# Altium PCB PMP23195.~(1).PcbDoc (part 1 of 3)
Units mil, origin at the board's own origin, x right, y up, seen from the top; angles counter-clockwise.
Board outline 3600 x 3000 mil, 4 copper layers (Top Layer, Signal Layer 1, Signal Layer 2, Bottom Layer), stack 39.6 mil thick; 143 components, 62 nets, 279 pads, 97 vias.
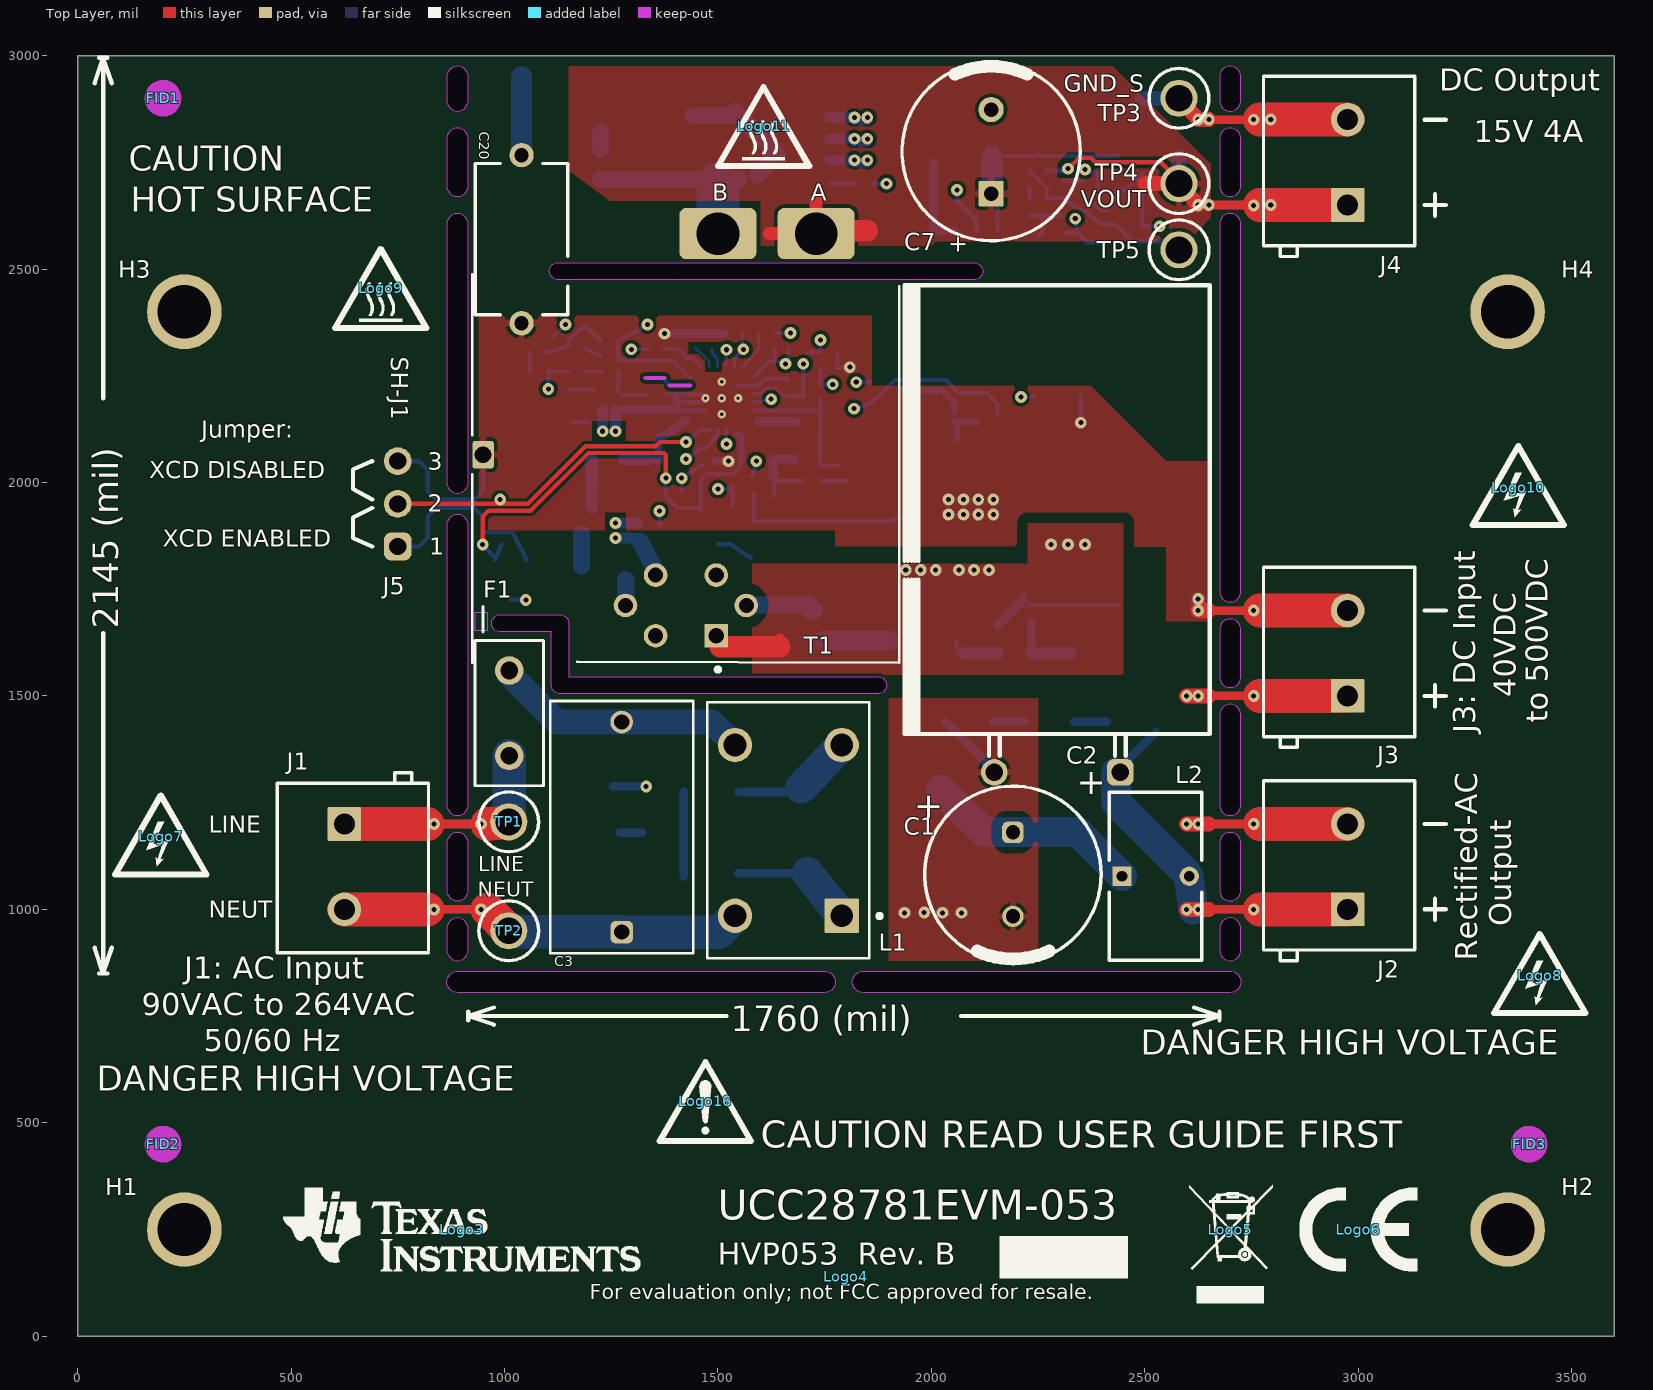
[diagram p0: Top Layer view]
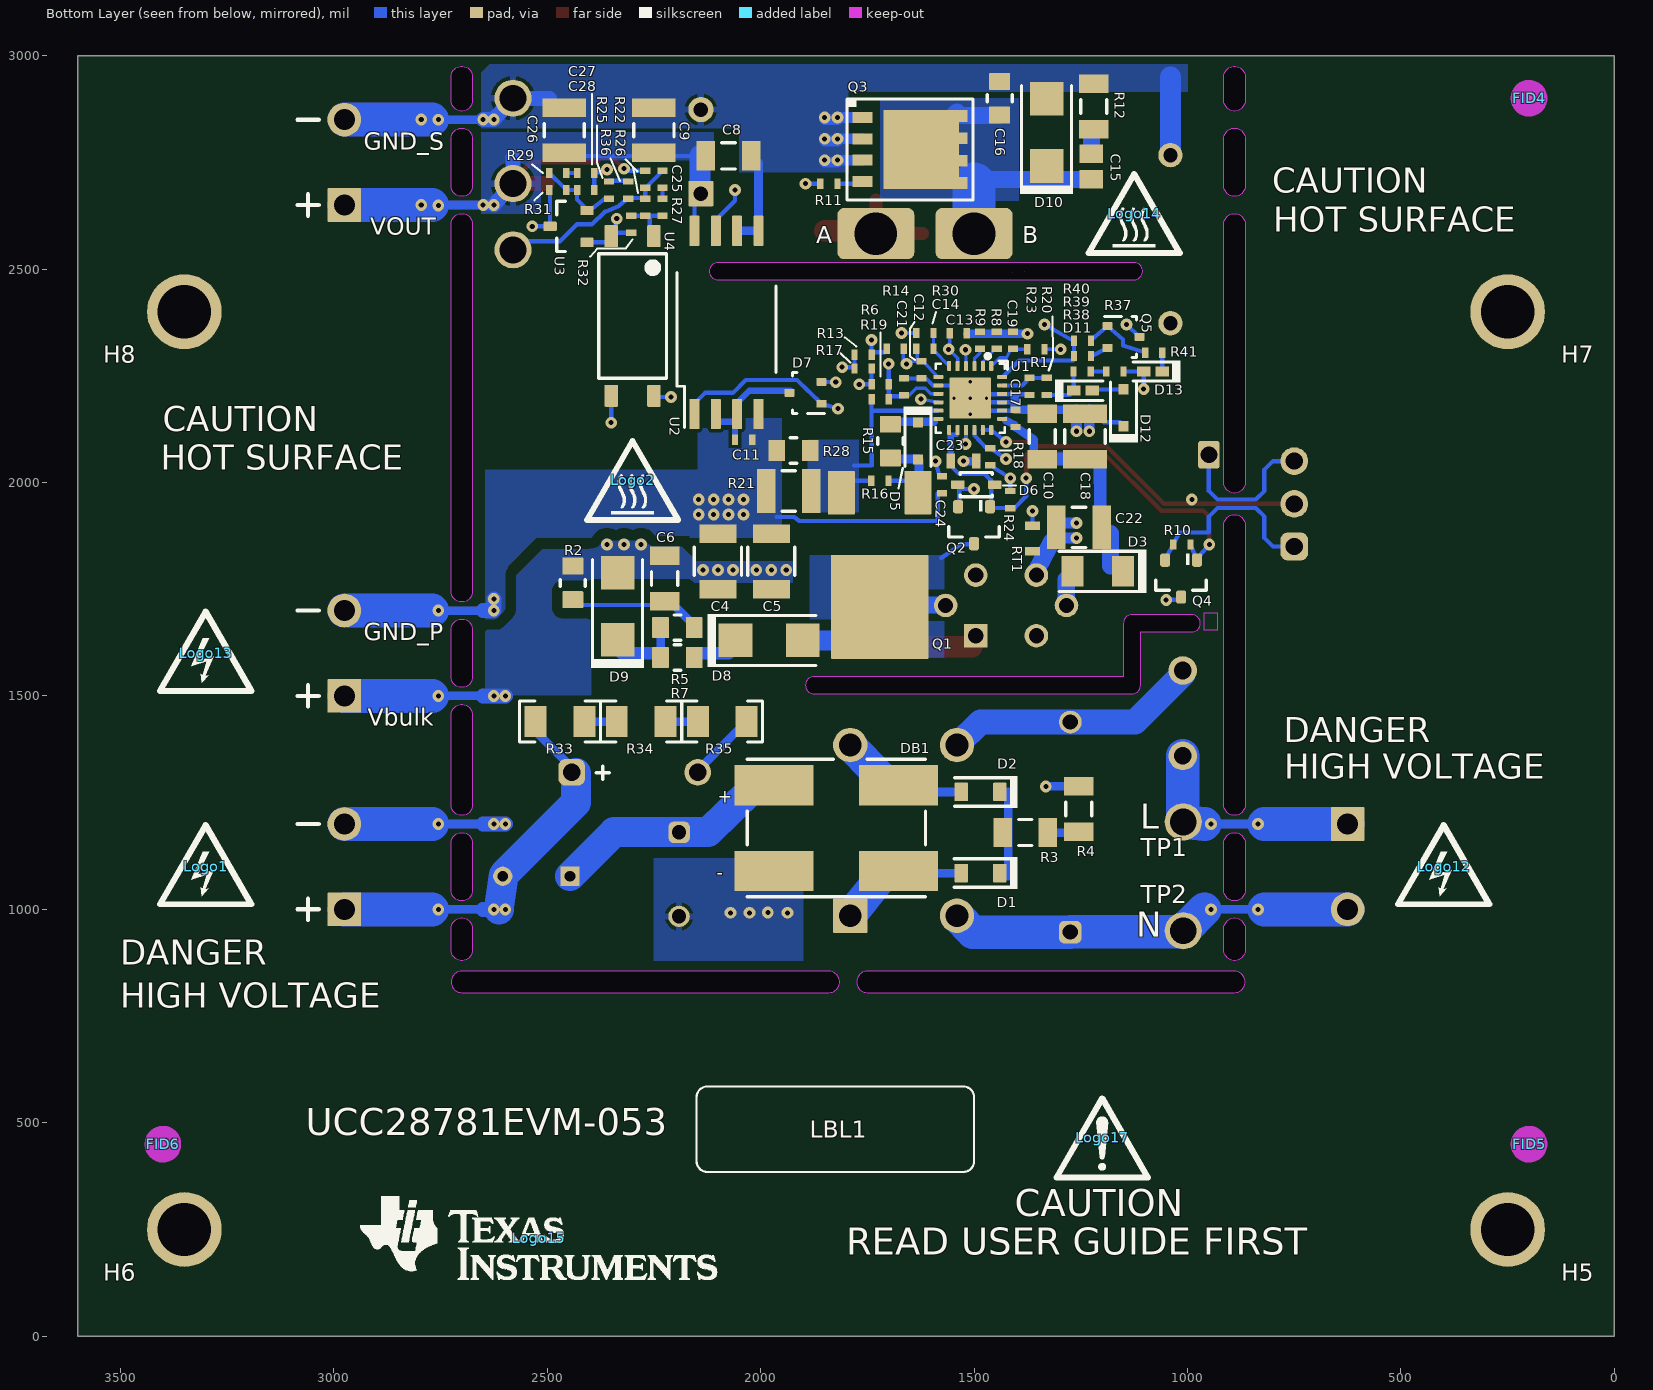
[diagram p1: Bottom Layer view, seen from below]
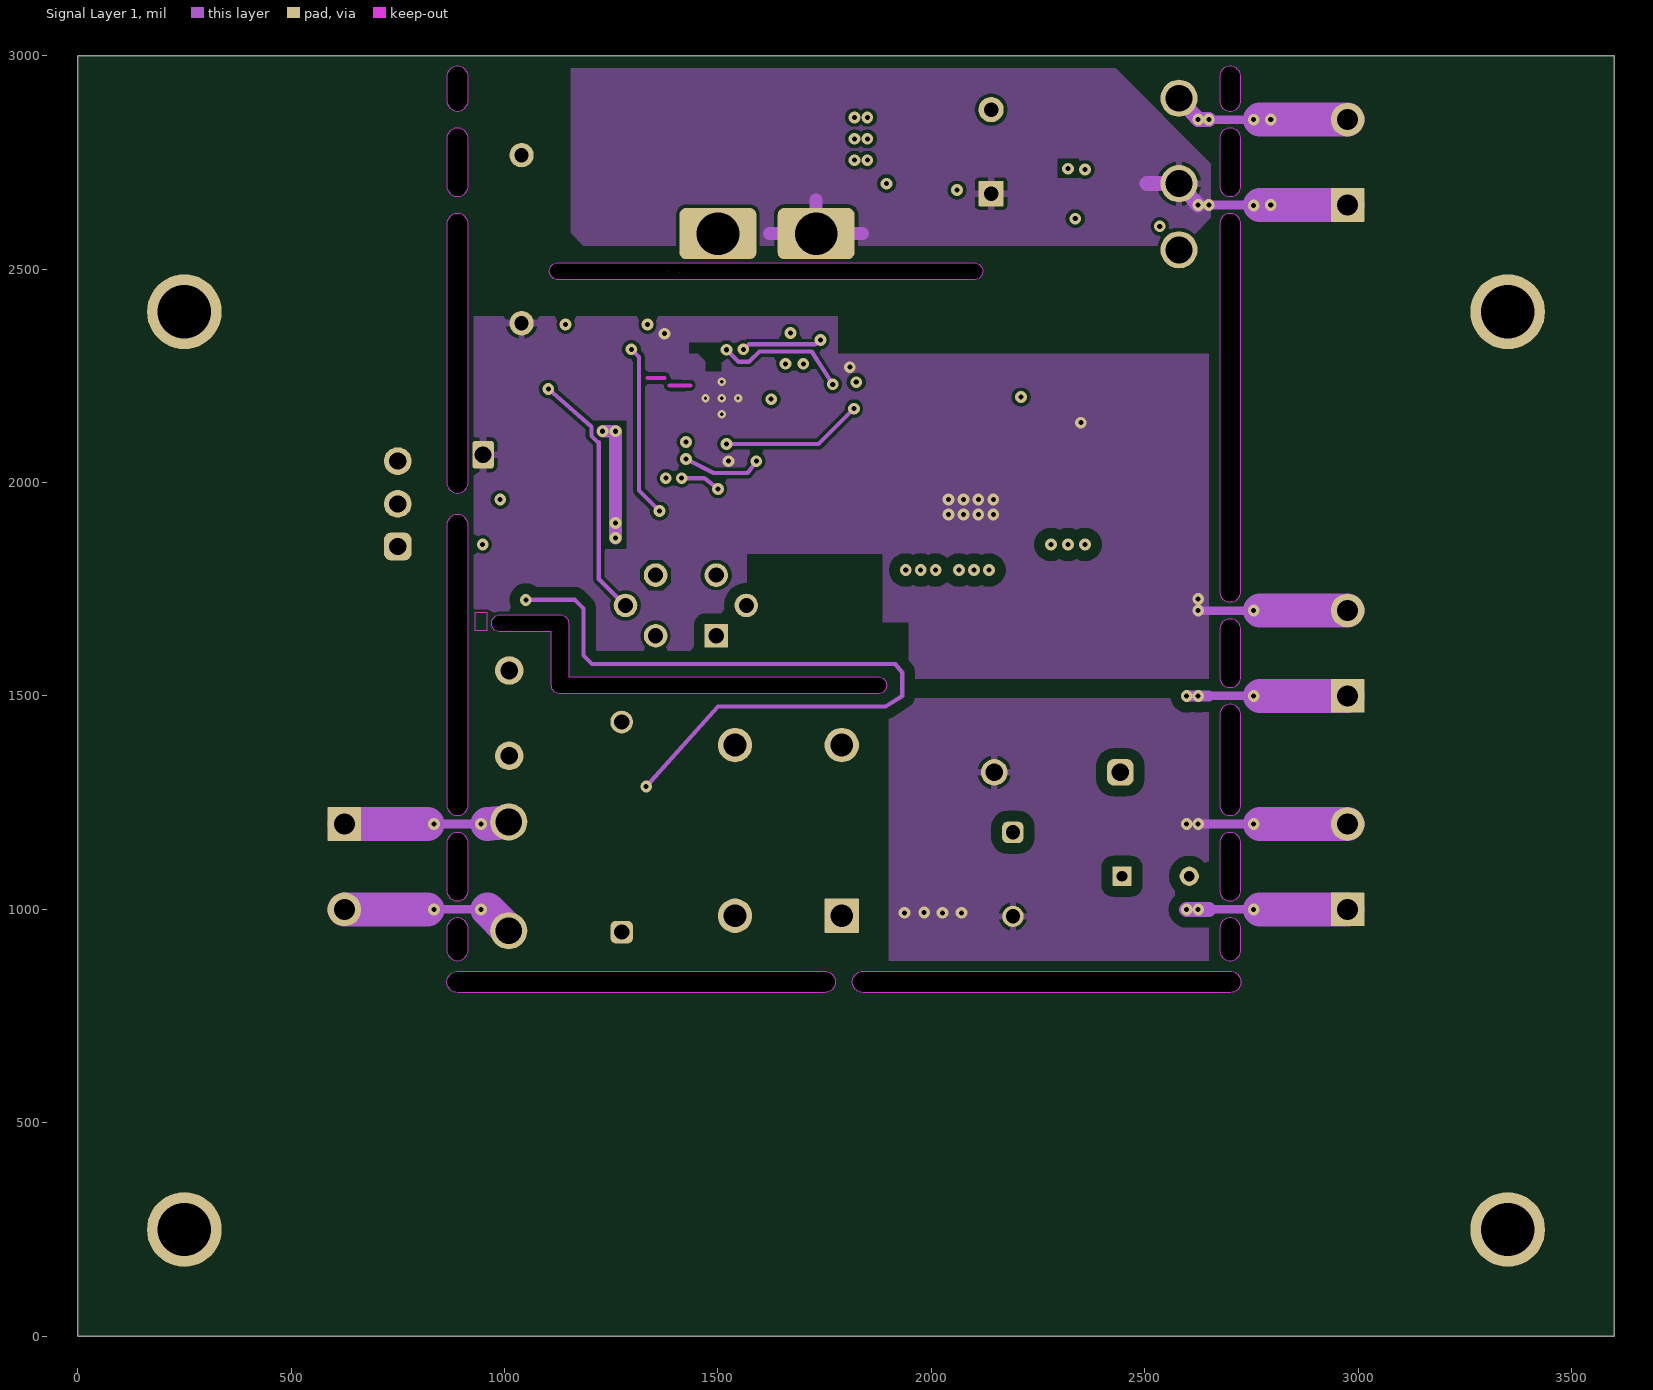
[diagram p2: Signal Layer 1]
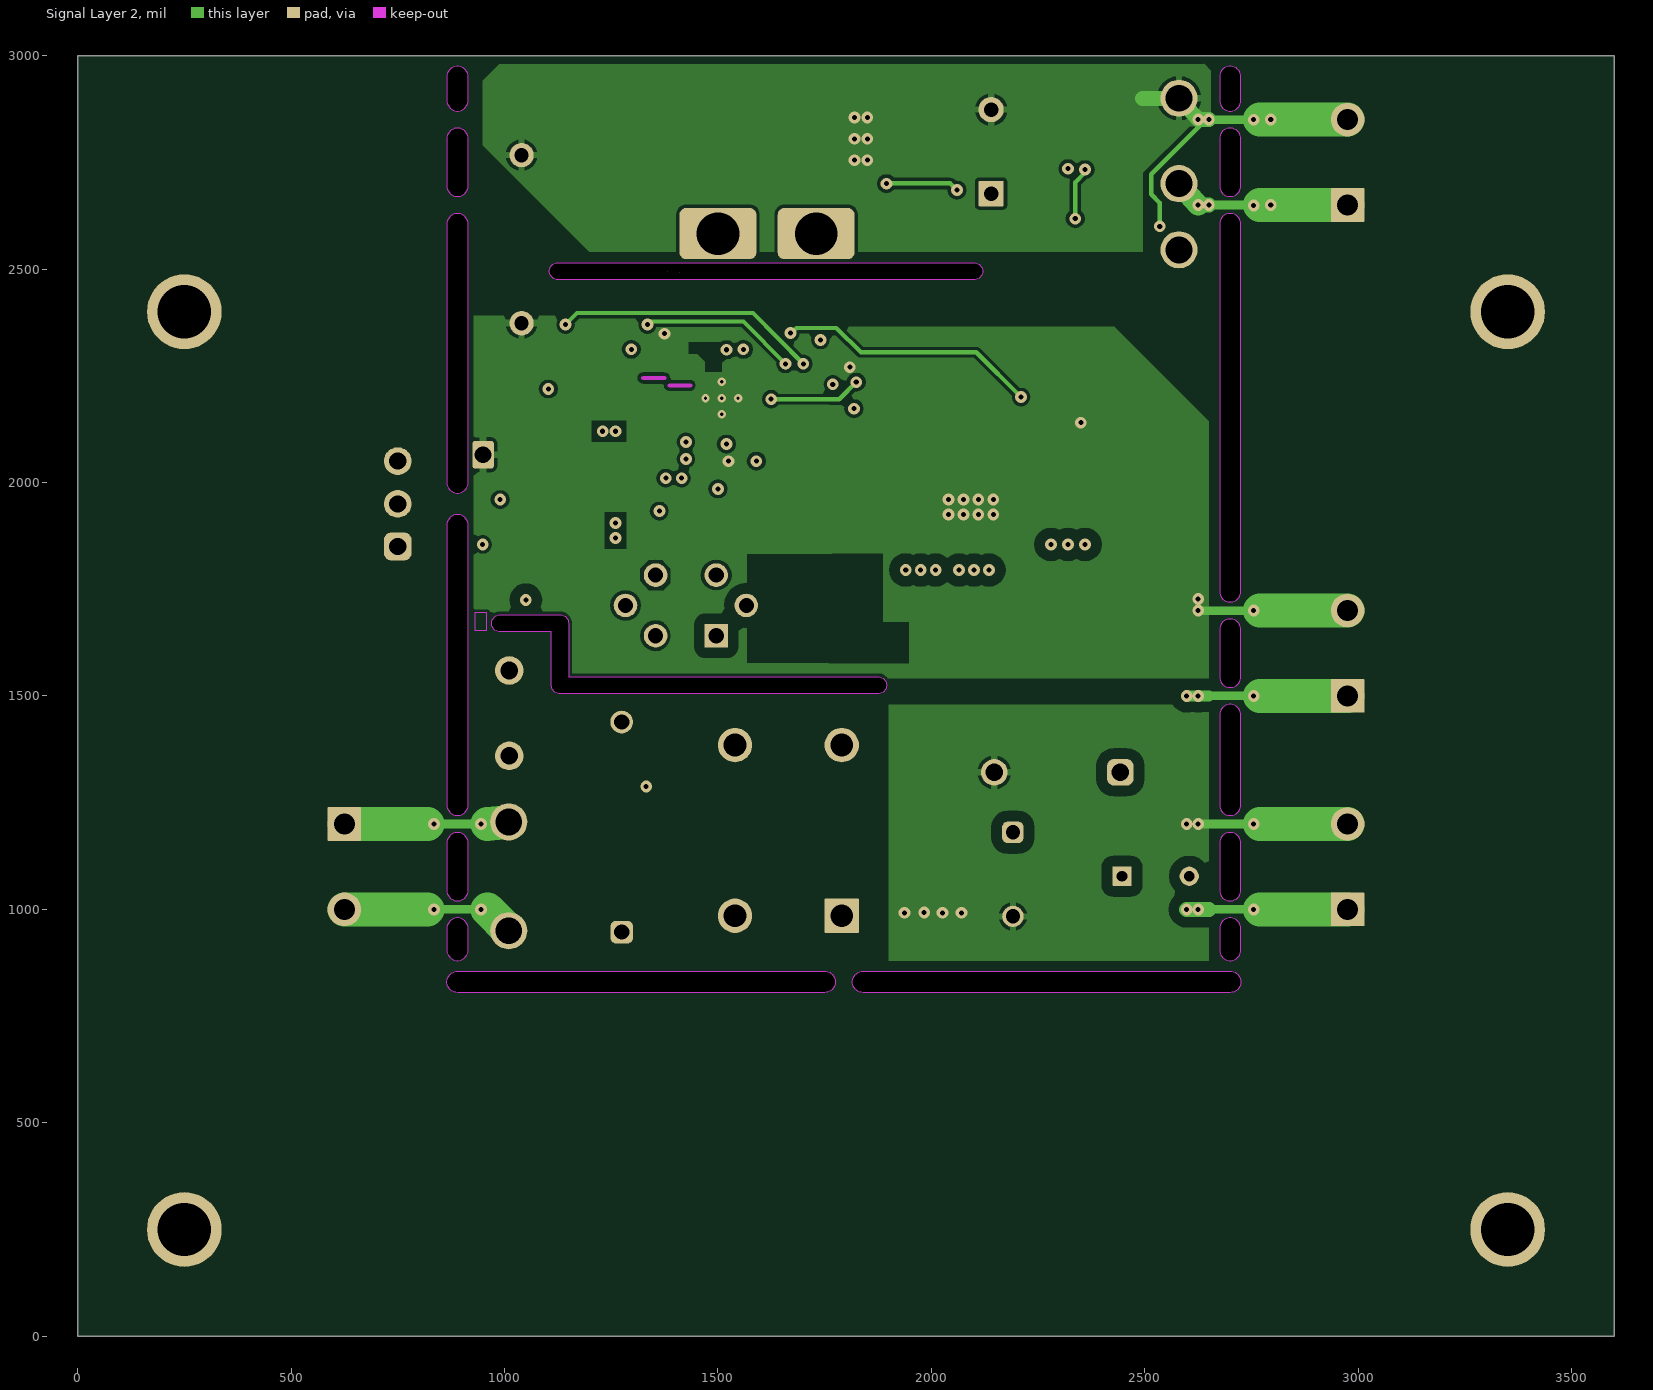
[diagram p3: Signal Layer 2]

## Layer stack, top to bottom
Top Solder: solder mask 0.4, Solder Resist, Dk 3.5
Top Layer: signal copper 1.4
Dielectric 1: prepreg 8, FR-4, Dk 4.2
Signal Layer 1: signal copper 1.4
Dielectric 2: core 18, FR-4, Dk 4.2
Signal Layer 2: signal copper 1.4
Dielectric 3: prepreg 8, FR-4, Dk 4.2
Bottom Layer: signal copper 1.4
Bottom Solder: solder mask 0.4, Solder Resist, Dk 3.5

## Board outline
0,0 3600,0 3600,3000 0,3000
cut-out: 2674.99,2895 ccw(c2700,2895) 2725.01,2895 2725.01,2950 ccw(c2700,2950) 2674.99,2950
cut-out: 2674.99,2695 ccw(c2700,2695) 2725.01,2695 2725.01,2805 ccw(c2700,2805) 2674.99,2805
cut-out: 2674.99,1545 ccw(c2700,1545) 2725.01,1545 2725.01,1655 ccw(c2700,1655) 2674.99,1655
cut-out: 2674.99,1245 ccw(c2700,1245) 2725.01,1245 2725.01,1455 ccw(c2700,1455) 2674.99,1455
cut-out: 2674.99,1045 ccw(c2700,1045) 2725.01,1045 2725.01,1155 ccw(c2700,1155) 2674.99,1155
cut-out: 2674.99,905 ccw(c2700,905) 2725.01,905 2725.01,955 ccw(c2700,955) 2674.99,955
cut-out: 1840,804.99 cw(c1840,830) 1840,855.01 2700,855.01 cw(c2700,830) 2725.01,830 cw(c2700,830) 2700,804.99
cut-out: 890,804.99 cw(c890,830) 890,855.01 1750,855.01 cw(c1750,830) 1775.01,830 cw(c1750,830) 1750,804.99
cut-out: 864.98,905 ccw(c890,905) 915.02,905 915.02,955 ccw(c890,955) 864.98,955
cut-out: 864.98,1045 ccw(c890,1045) 915.02,1045 915.02,1155 ccw(c890,1155) 864.98,1155
cut-out: 864.98,1245 ccw(c890,1245) 915.02,1245 915.02,1900 ccw(c890,1900) 864.98,1900
cut-out: 864.98,2695 ccw(c890,2695) 915.02,2695 915.02,2805 ccw(c890,2805) 864.98,2805
cut-out: 864.98,2000 ccw(c890,2000) 915.02,2000 915.02,2605 ccw(c890,2605) 864.98,2605
cut-out: 864.98,2895 ccw(c890,2895) 915.02,2895 915.02,2950 ccw(c890,2950) 864.98,2950
cut-out: 2674.99,1745 ccw(c2700,1745) 2725.01,1745 2725.01,2605 ccw(c2700,2605) 2674.99,2605
cut-out: 1125,2474.99 cw(c1125,2495) 1125,2515.01 2100,2515.01 cw(c2100,2495) 2120.01,2495 cw(c2100,2495) 2100,2474.99
cut-out: 1109.98,1525 1109.98,1649.99 990,1649.99 cw(c990,1670) 990,1690.01 1130,1690.01 cw(c1130,1670) 1150.02,1670 1150.02,1545.01 1875,1545.01 cw(c1875,1525) 1895.01,1525 cw(c1875,1525) 1875,1504.99 1130,1504.99 cw(c1130,1525)
cut-out: 1381.53,2495
cut-out: 1410.62,2492

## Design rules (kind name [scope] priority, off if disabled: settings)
AcuteAngle [All] p1: minimum=5.00000000000000E+0000 checktracksonly=FALSE
AssemblyTestPointUsage [All] p1: valid=2
BoardOutlineClearance BoardOutlineClearance_MountingHoles [OnCopper and InComponentClass('Mounting Holes')] p1: gap=15 ignorepadtopadclearanceinfootprint=FALSE
BoardOutlineClearance BoardOutlineClearance_Poly [OnCopper and InPoly] p2: gap=3.94 ignorepadtopadclearanceinfootprint=FALSE
BoardOutlineClearance [OnCopper and Not InComponentClass('Logo') and not InComponentClass('FiducialMark') and not InRegion(1000,500,4000,800)] p3: gap=4.53 ignorepadtopadclearanceinfootprint=FALSE
Clearance Clearance_HV [InNetClass('HV') vs not OnMultiLayer] p1: gap=25 ignorepadtopadclearanceinfootprint=TRUE // 1mm Clearance
Clearance Clearance_Keepouts [((IsTrack Or IsArc) And Not InPoly) And IsFree and IsKeepOut vs ((IsTrack Or IsArc) And Not InPoly) And IsFree and IsKeepOut] p2: gap=0 ignorepadtopadclearanceinfootprint=FALSE
Clearance Clearance_Poly [InPolygon] p3: gap=8 ignorepadtopadclearanceinfootprint=FALSE except(0: Arc-Hole Track-Hole SMDPad-Hole THPad-Hole Via-Hole Fill-Hole Poly-Hole Region-Hole Text-Hole)
Clearance [not InComponentClass('FiducialMark') vs not InComponentClass('FiducialMark')] p4: gap=6 ignorepadtopadclearanceinfootprint=FALSE
ComponentClearance ComponentClearance_MountingHoles_FiducialMarks [InComponentClass('Mounting Holes') vs InComponentClass('FiducialMark')] p1: gap=10 collisioncheckmode=3 verticalgap=10 showdistances=FALSE
ComponentClearance ComponentClearance_Shunt [InComponentClass('Header') vs InComponentClass('Shunt')] p2: gap=0 collisioncheckmode=3 verticalgap=0 showdistances=FALSE
ComponentClearance ComponentClearance_Logo [InComponentClass('Logo')] p3: gap=5 collisioncheckmode=3 verticalgap=0 showdistances=FALSE
ComponentClearance ComponentClearance_ScrewToNut [(HasFootprint('NY PMS 440 0025 PH')) vs (HasFootprint('Keystone_1902C'))] p4: gap=5 collisioncheckmode=3 verticalgap=10 showdistances=FALSE
ComponentClearance ComponentClearance_MountingHoles [InComponentClass('Mounting Holes')] p5: gap=10 collisioncheckmode=3 verticalgap=100000 showdistances=FALSE
ComponentClearance ComponentClearance_SmallPassives [HasFootprint('0201*') or HasFootprint('0402*') or HasFootprint('0508') or HasFootprint('0603*') or HasFootprint('0612') or HasFootprint('0805*') or HasFootprint('0815*') or HasFootprint('0830*') or HasFootprint('1206*') or HasFootprint('1210*') or HasFootprint('1808*') or HasFootprint('1812*') or HasFootprint('1825*') or HasFootprint('2010*') or HasFootprint('2220*') or HasFootprint('2225*') or HasFootprint('2512*') or HasFootprint('2728*') or HasFootprint('3518*') vs HasFootprint('0201*') or HasFootprint('0402*') or HasFootprint('0508') or HasFootprint('0603*') or HasFootprint('0612') or HasFootprint('0805*') or HasFootprint('0815*') or HasFootprint('0830*') or HasFootprint('1206*') or HasFootprint('1210*') or HasFootprint('1808*') or HasFootprint('1812*') or HasFootprint('1825*') or HasFootprint('2010*') or HasFootprint('2220*') or HasFootprint('2225*') or HasFootprint('2512*') or HasFootprint('2728*') or HasFootprint('3518*')] p6: gap=8 collisioncheckmode=3 verticalgap=10 showdistances=FALSE
ComponentClearance ComponentClearance_THtoSMT [IsThruComponent vs IsSMTComponent] p7: gap=10 collisioncheckmode=3 verticalgap=30 showdistances=FALSE
ComponentClearance ComponentClearance_THtoTH [IsThruComponent vs IsThruComponent] p8: gap=2 collisioncheckmode=3 verticalgap=30 showdistances=FALSE
ComponentClearance [All] p9: gap=8 collisioncheckmode=3 verticalgap=10 showdistances=FALSE
DiffPairsRouting [All] p1: maxlimit=100 minlimit=10 mostfreqgap=10 toplayer_minwidth=15 toplayer_maxwidth=15 toplayer_prefwidth=15 midlayer1_minwidth=15 midlayer1_maxwidth=15 midlayer1_prefwidth=15 midlayer2_minwidth=15 midlayer2_maxwidth=15 midlayer2_prefwidth=15 bottomlayer_minwidth=15 bottomlayer_maxwidth=15 bottomlayer_prefwidth=15 maxuncoupledlength=1000
FabricationTestPointUsage TestPointUsage [All] p1: valid=2 allowmultiple=FALSE
FabricationTestpoint Testpoint [All] p1: side=3 testpointundercomponent=TRUE minsize=40 maxsize=100 preferedsize=60 minholesize=0 maxholesize=40 preferedholesize=32 testpointgrid=1 allowsidetop=TRUE allowsidebottom=TRUE usegrid=TRUE gridtolerance=0.01
FanoutControl Fanout_LCC [IsLCC] p1: bgadir=Out bgaviamode=Centered fanoutstyle=Auto fanoutdirection=Alternating viagrid=1 // Fanout_LCC (Default Rule)
FanoutControl Fanout_BGA [IsBGA] p2: bgadir=Out bgaviamode=Centered fanoutstyle=Auto fanoutdirection=Alternating viagrid=1 // Fanout_BGA (Default Rule)
FanoutControl Fanout_Default [All] p4: bgadir=Out bgaviamode=Centered fanoutstyle=Auto fanoutdirection=Alternating viagrid=1 // Fanout_Default (Default Rule)
FanoutControl Fanout_Small [(CompPinCount < 5)] p5: bgadir=Out bgaviamode=Centered fanoutstyle=Auto fanoutdirection=OutThenIn viagrid=1 // Fanout_Small (Default Rule)
HoleSize [All] p1: absolutevalues=TRUE maxlimit=251 minlimit=7.87 maxpercent=80.000 minpercent=20.000
HoleToHoleClearance [All] p1: gap=7.87 allowstackedmicrovias=TRUE
MinimumAnnularRing MinimumAnnularRing_ThermalPadVias [IsVia and InAnyComponent] p1: minimumring=5.91
MinimumAnnularRing [All] p2: minimumring=5
MinimumSolderMaskSliver MinimumSolderMaskSliver_Logo [InComponentClass('Logo') vs InComponentClass('Logo')] p1: minsoldermaskwidth=0
MinimumSolderMaskSliver [All] p2: minsoldermaskwidth=1
PlaneConnect [All] p1: planeconnectstyle=Direct reliefexpansion=10 reliefentries=4 reliefconductorwidth=10 reliefairgap=10
PolygonConnect [All] p1: thpad.connectstyle=Relief thpad.reliefconductorwidth=15.75 thpad.reliefentries=4 thpad.polygonreliefangle="90 Angle" thpad.airgapwidth=7.87 smdpad.connectstyle=Direct smdpad.reliefconductorwidth=10 smdpad.reliefentries=4 smdpad.polygonreliefangle="90 Angle" smdpad.airgapwidth=10 via.connectstyle=Direct via.reliefconductorwidth=10 via.reliefentries=4 via.polygonreliefangle="90 Angle" via.airgapwidth=10
RoutingVias ThermalPadVias [IsVia and InAnyComponent] p1: holewidth=7.87 width=19.68 viastyle="Through Hole" minholewidth=7.87 minwidth=19.68 maxholewidth=12.99 maxwidth=23.62
RoutingVias [All] p2: holewidth=16 width=34 viastyle="Through Hole" minholewidth=7.87 minwidth=26 maxholewidth=40 maxwidth=65
SilkToBoardRegionClearance [Not ((IsComment or IsDesignator) And (Hide <> 'False')) and not InRegion(1000,500,4000,800)] p1:
SilkToSilkClearance SilkToSilkClearance_Pb-FreeLogo [(HasFootprint('Pb-Free_Overlay_Medium') OR HasFootprint('Pb-Free_Overlay_Small')) vs (HasFootprint('Pb-Free_Overlay_Medium') OR HasFootprint('Pb-Free_Overlay_Small'))] p1: silktosilkclearance=0
SilkToSilkClearance [All] p2: silktosilkclearance=0.5
SilkToSolderMaskClearance SilkToComponentPadClearance [IsPad and InAnycomponent] p1: minsilkscreentomaskgap=0.5 clearancetoexposedcopper=TRUE
SilkToSolderMaskClearance "Silk to Solder Mask Opening" [All] p2: minsilkscreentomaskgap=0 clearancetoexposedcopper=FALSE
SolderMaskExpansion [All] p1: expansion=1.97
Width [All] p1: maxlimit=100 minlimit=5 preferedwidth=10 checkconnectedcopper=TRUE
14 further rules are at their usual default settings.

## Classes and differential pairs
component class "Mounting Holes": H1 H2 H3 H4
component class Logo: Logo3 Logo15
component class Label: LBL1
component class Header: J5
component class FiducialMark: FID1 FID2 FID3 FID4 FID5 FID6
component class AssemblyNote: ZZ1 ZZ2 ZZ3 ZZ4
component class HVP053B_Hardware: !PCB1 FID1 FID2 FID3 FID4 FID5 FID6 H1 H2 H3 H4 H5 H6 H7 H8 LBL1 Logo3 Logo4 Logo5 Logo6 Logo7 Logo8 Logo9 Logo10 Logo11 Logo12 Logo13 Logo14 Logo15 Logo17 ZZ1 ZZ2 ZZ3 ZZ4
net class Secondary: GND_S
net class Primary: GND_P
net class HV: NetC1_1 NetQ4_3 Vbulk Vbulk0 Vswn
component class HVP053B_sheet1: C1 C2 C3 C4 C5 C6 C7 C8 C9 C10 C11 C12 C13 C14 C15 C16 C17 C18 C19 C20 C21 C22 C23 C24 C25 C26 C27 C28 C? D1 D2 D3 D5 D6 D7 D8 D9 D10 D11 D12 D13 D? DB1 F1 J1 J2 J3 J4 J5 L1 L2 LOGO1 LOGO2 Logo16 Q1 Q2 Q3 Q4 Q5 Q? R1 R2 R3 R4 R5 R6 R7 R8 R9 R10 R11 R12 R13 R14 R15 R16 R17 R18 R19 R20 R21 R22 R23 R24 R25 R26 R27 R28 R29 R30 R31 R32 R33 R34 R35 R36 R37 R38 R39 R40 R41 R? RT1 SH-J1 T1 TP1 TP2 TP3 TP4 TP5 TP? U1 U2 U3 U4 U?

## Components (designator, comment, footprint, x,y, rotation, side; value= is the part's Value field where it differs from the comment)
C1 "UVC2G150MPD" UVC_1000x1600 2191,1082 r270 top value=15uF
C2 "400BXW82MEFR18X25" Rubycon_1800x2500_HD 2295,1321 r180 top locked value=82uF
C3 "890324024003" WCAP-FTX2_1500x850 1274.58,1192.8 r90 top value=0.33uF
C4 "C1210C104KBRAC7800" 1210_280 2100,1815 r270 bottom value=0.1uF
C5 "C1210C104KBRAC7800" 1210_280 1975,1815 r270 bottom value=0.1uF
C6 "GRM31BR72J102KW01L" 1206L 2225,1775 r270 bottom value=1000pF
C7 "APSG200ELL681MJB5S" PSG_1000x1150 2140,2775 r90 top value=680uF
C8 "C1206C106J3RACAUTO" 1206_180L 2075,2765 r180 bottom value=10uF
C9 "GRM32ER71E226KE15L" 1210_270L 2250,2825 r90 bottom value=22uF
C10 "C3216X5R1H106K160AB" 1206_180L 1340,2108 r90 bottom value=10uF
C11 "GRM155R71H104ME14D" 0402S 2040,2100 r180 bottom value=0.1uF
C12 "GRM155R71C224KA12D" 0402S 1623,2264 r270 bottom value=0.22uF
C13 "GRM155R71H331KA01D" 0402S 1537.14,2349.3 r180 bottom value=330pF
C14 "GRM155R71H331KA01D" 0402S 1615,2313 r180 bottom value=330pF
C15 "GRM21AR72E102KW01D" 0805L 1225,2740 r270 bottom value=1000pF
C16 "GRM21AR72E152KW01D" 0805_HV1 1440,2900 r90 bottom value=1500pF
C17 "GRM155R71H104ME14D" 0402S 1403,2150 r90 bottom value=0.1uF
C18 "GMK325BJ226MM-P" 1210L 1240,2108 r270 bottom value=22uF
C19 "GRM1555C1H101JA01D" 0402S 1409,2333 r270 bottom value=100pF
C20 "C921U222MVVDBA7317" C900_9x13 1040,2570 r270 top locked value=2200pF
C21 "GRM1555C1H101JA01D" 0402S 1664,2224 r90 bottom value=100pF
C22 "GMK325BJ226MM-P" 1210L 1254.15,1895 r180 bottom value=22uF
C23 "CGA3E1X7R1V105K080AC" 0603S 1525,2050 r180 bottom value=1uF
C24 "GCM1555C1H220JA16D" 0402S 1575,1995 r90 bottom value=22pF
C25 "GRM155R71H153KA12D" 0402S 2230,2710 r90 bottom value=0.015uF
C26 "GRM32ER71E226KE15L" 1210_270L 2460,2825 r90 bottom value=22uF
C27 "GRM155R71H103KA88D" 0402S 2410,2725 r180 bottom value=0.01uF
C28 "GCM1555C1H220JA16D" 0402S 2410,2685 r0 bottom value=22pF
D1 "RFU02VSM6STR" TUMD2SM 1485,1085 r0 bottom value=600V
D2 "RFU02VSM6STR" TUMD2SM 1484.81,1275 r0 bottom value=600V
D3 "CSFMT104-HF" SOD-123H 1210,1792 r0 bottom value=200V
D5 "BAS316,115" SOD-323 1631,2097 r270 bottom value=100V
D6 "CDSOD323-T18C" FP-CDSOD323-T18C_SOD323-MFG 1495,1995 r180 bottom value=18V
D7 "BAS40W-05-7-F" SOT-323 1895,2210 r0 bottom value=40V
D8 "MRA4007T3G" SMA 1980,1630 r180 bottom value=1000V
D9 "SMAJ150A" SMA 2335,1710 r90 bottom value=150V
D10 "SMAJ120A" SMA 1330,2820 r90 bottom value=120V
D11 "1N4148X-TP" SOD-523 1245,2215 r180 bottom value=75V
D12 "SZMM3Z27VST1G" SOD-323 1150,2175 r90 bottom value=27V
D13 "BZT585B39T-7" SOD-523 1081,2260 r0 bottom value=39V
DB1 "Z4DGP406L-HF" Z4-D 1822.57,1190.39 r180 bottom value=600V
F1 "39213150000" FUSE_392 1011.02,1459.54 r270 top
FID1 "Fiducial" Fiducial6.4-20 200,2900 r0 top locked
FID2 "Fiducial" Fiducial6.4-20 200,450 r0 top locked
FID3 "Fiducial" Fiducial6.4-20 3400,450 r0 top locked
FID4 "Fiducial" Fiducial6.4-20 200,2900 r180 bottom locked
FID5 "Fiducial" Fiducial6.4-20 200,450 r180 bottom locked
FID6 "Fiducial" Fiducial6.4-20 3400,450 r180 bottom locked
H1 "NY PMS 440 0025 PH" "NY PMS 440 0025 PH" 250,250 r0 top
H2 "NY PMS 440 0025 PH" "NY PMS 440 0025 PH" 3350,250 r0 top
H3 "NY PMS 440 0025 PH" "NY PMS 440 0025 PH" 250,2400 r0 top
H4 "NY PMS 440 0025 PH" "NY PMS 440 0025 PH" 3350,2400 r0 top
H5 "1902C" Keystone_1902C 250,250 r0 bottom
H6 "1902C" Keystone_1902C 3350,250 r0 bottom
H7 "1902C" Keystone_1902C 250,2400 r0 bottom
H8 "1902C" Keystone_1902C 3350,2400 r0 bottom
J1 "ED120/2DS" On-Shore_ED120_2DS 625,1100 r270 top
J2 "ED120/2DS" On-Shore_ED120_2DS 2975,1100 r90 top
J3 "ED120/2DS" On-Shore_ED120_2DS 2975,1600 r90 top
J4 "ED120/2DS" On-Shore_ED120_2DS 2975,2750 r90 top
J5 "TSW-103-07-G-S" TSW-103-07-G-S 750,1950 r90 top
L1 "RLTI-1387" FP-RLTI-1387_PTH_CMC_0IN38_0IN60-MFG 1665,1185 r90 top
L2 "7447052" FP-7447052_PTH_D10MM0-MFG 2525.33,1077.65 r90 top
LBL1 "THT-14-423-10" Label_650x200 1825,485 r180 bottom
Logo1 "DANGER HIGH VOLTAGE" IEC_HighVoltage_Small 3300,1100 r180 bottom
Logo2 "CAUTION HOT SURFACE" IEC_HotSurface_Small 2300,2005 r180 bottom
Logo3 "Texas Instruments + Symbol" TI_Stacked_Overlay_Small 900,250 r0 top
Logo4 "FCC disclaimer" FCC_disclaimer 1800,140 r0 top
Logo5 "WEEE logo" WEEE_Minimum 2700,250 r0 top
Logo6 "CE Mark" CE_Mark_5mm 3000,250 r0 top
Logo7 "DANGER HIGH VOLTAGE" IEC_HighVoltage_Small 195,1170 r0 top
Logo8 "DANGER HIGH VOLTAGE" IEC_HighVoltage_Small 3425,845 r0 top
Logo9 "CAUTION HOT SURFACE" IEC_HotSurface_Small 710,2455 r0 top
Logo10 "DANGER HIGH VOLTAGE" IEC_HighVoltage_Small 3375,1988 r0 top
Logo11 "CAUTION HOT SURFACE" IEC_HotSurface_Small 1607,2834 r0 top
Logo12 "DANGER HIGH VOLTAGE" IEC_HighVoltage_Small 400,1100 r180 bottom
Logo13 "DANGER HIGH VOLTAGE" IEC_HighVoltage_Small 3300,1600 r180 bottom
Logo14 "CAUTION HOT SURFACE" IEC_HotSurface_Small 1125,2630.02 r180 bottom
Logo15 "Texas Instruments + Symbol" TI_Stacked_Overlay_Small 2520,230 r180 bottom
Logo16 "CAUTION.  READ USER GUIDE BEFORE USE" IEC_Caution_Small 1470.58,550 r0 top
Logo17 "CAUTION.  READ USER GUIDE BEFORE USE" IEC_Caution_Small 1200,465 r180 bottom
Q1 "IPD80R600P7ATMA1" DPAK 1721.2,1842.41 r270 bottom value=800V
Q2 "CPC3982TTR" SOT-23L 1500,1900 r270 bottom value=800V
Q3 "BSC093N15NS5ATMA1" PG-TDSON-8 1650,2780 r180 bottom value=150V
Q4 "BSS126H6327XTSA2" SOT-23L 1015,1775 r270 bottom value=600V
Q5 "MMST3906-7-F" SOT-323 1150.02,2341 r180 bottom value="40 V"
R1 "CRCW04023K32FKED" 0402S 1355,2312 r0 bottom value=3.32k
R2 "CRCW0805470KJNEA" 0805_HV1 2440,1765 r90 bottom value=470k
R3 "CRCW120613K0JNEA" 1206L 1380,1180 r180 bottom value=13k
R4 "CRCW120613K0JNEA" 1206L 1255,1235 r90 bottom value=13k
R5 "CRCW080515R0JNEA" 0805_HV1 2195,1660 r180 bottom value=15
R6 "CRCW04021M00JNED" 0402S 1720,2230 r180 bottom value=1.0Meg
R7 "CRCW080515R0JNEA" 0805_HV1 2195,1590 r0 bottom value=15
R8 "CRCW0402169KFKED" 0402S 1446.59,2332.88 r270 bottom value=169k
R9 "CRCW040293K1FKED" 0402S 1485.96,2332.88 r270 bottom value=93.1k
R10 "CRCW04021M00JNED" 0402S 1013,1855 r180 bottom value=1.0Meg
R11 "CRCW040210R0JNED" 0402S 1840,2700 r180 bottom value=10
R12 "CRCW120610R0JNEA" 1206L 1220,2880.81 r270 bottom value=10
R13 "CRCW040239K2FKED" 0402S 1760,2299 r0 bottom value=39.2k
R14 "CRCW0402191KFKED" 0402S 1685,2313 r0 bottom value=191k
R15 "CRCW0805100RJNEA" 0805_HV1 1696,2097 r270 bottom value=100
R16 "CRCW040210K0FKED" 0402S 1720.41,2003.83 r180 bottom value=10.0k
R17 "CRCW04020000Z0EDHP" 0402S 1760,2267 r180 bottom value=0
R18 "CRCW0402511RFKED" 0402S 1462,2060 r270 bottom value=511
R19 "CRCW0402402RFKED" 0402S 1720,2195 r0 bottom value=402
R20 "CRCW040215K4FKED" 0402S 1330,2225 r90 bottom value=15.4k
R21 "MCR25JZHFLR220" 1210L 1934,1980 r180 bottom value=0.22
R22 "RC0402JR-070RL" 0402S 2270,2710 r270 bottom value=0
R23 "CRCW04026K98FKED" 0402S 1370,2225 r90 bottom value=6.98k
R24 "CRCW04021M00JNED" 0402S 1415,1960 r270 bottom value=1.0Meg
R25 "ERJ-2RKF1503X" 0402S 2355,2685 r90 bottom value=150k
R26 "CRCW040215K0FKED" 0402S 2270,2645 r90 bottom value=15.0k
R27 "CRCW0402511RFKED" 0402S 2230,2645 r90 bottom value=511
R28 "ERJ-6RQFR68V" 0805_HV1 1923,2075 r0 bottom value=0.68
R29 "CRCW040210K0FKED" 0402S 2475,2725 r0 bottom value=10.0k
R30 "CRCW040220K0FKED" 0402S 1615,2350 r0 bottom value=20.0k
R31 "CRCW040230K0FKED" 0402S 2475,2685 r0 bottom value=30.0k
R32 "CRCW04025K62FKED" 0402S 2303.15,2605 r90 bottom value=5.62k
R33 "CRCW1206220KJNEA" 1206 2470,1440 r0 bottom value=220k
R34 "CRCW1206220KJNEA" 1206 2280,1440 r0 bottom value=220k
R35 "CRCW1206220KJNEA" 1206 2090,1440 r0 bottom value=220k
R36 "CRCW0402102RFKED" 0402S 2310,2685 r90 bottom value=102
R37 "CRCW04022K10FKED" 0402S 1170,2260 r0 bottom value=2.10k
R38 "CRCW04022K10FKED" 0402S 1247,2260 r0 bottom value=2.10k
R39 "CRCW040227K4FKED" 0402S 1246,2296 r180 bottom value=27.4k
R40 "CRCW04021K00FKED" 0402S 1246,2332 r180 bottom value=1.00k
R41 "CRCW040210K0FKED" 0402S 1079,2304 r180 bottom value=10.0k
RT1 "NCP18WB473J03RB" 0603S 1362.93,1868.9 r270 bottom value=47k
SH-J1 "SNT-100-BK-T-H" SNT-100-BK-x-H 750,2000 r90 top
T1 "RLTI-1431" FP-RLTI-1431_PTH8_1IN0_0IN91-MFG 1425,2033 r180 top locked
TP1 "LINE" Keystone5011 1010,1205 r90 top
TP2 "NEUTRAL" Keystone5012 1010,950 r90 top
TP3 "GND_S" Keystone5011 2580,2900 r90 top
TP4 "VOUT" Keystone5012 2580,2700 r90 top
TP5 "VOUT_A" Keystone5012 2580,2545 r90 top
U1 "UCC28781QRTWRQ1" RTW0024B-MFG 1508.96,2197.72 r270 bottom
U2 "UCC5304DWV" DWV0008A 2080,2375 r90 bottom locked
U3 "ATL431AIDBZR" DBZ0003A_L 2450,2600 r0 bottom
U4 "TLP383(GR-TPL,E" FP-TLP383(GR-TPL,E_SO6-4-MFG 2300,2390 r270 bottom locked
ZZ1 "These assemblies are ESD sensitive, ESD precautions shall be observed." AssemblyNote 4000,800 r0 top
ZZ2 "These assemblies must be clean and free from flux and all contaminants. Use of no clean flux is not acceptable." AssemblyNote 4000,600 r0 top
ZZ3 "These assemblies must comply with workmanship standards IPC-A-610 Class 2, unless otherwise specified." AssemblyNote 4000,400 r0 top
ZZ4 "Default installation of XCD configuration jumper SH-J1 to be in \"XCD DISABLED\" position on J5 (across pins 2-3)." AssemblyNote 4000,200 r0 top

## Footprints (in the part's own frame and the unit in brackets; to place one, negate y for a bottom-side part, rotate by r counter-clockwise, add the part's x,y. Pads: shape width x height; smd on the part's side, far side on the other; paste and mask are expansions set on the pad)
0402S [mil] "Based on C0402S footprint from PADS legacy"
  rect 15x24 smd: 1(-20,0) 2(20,0)
  body extent -22,-12 22,12, height 24
0603S [mil]
  rect 20x35 smd: 1(-30,0) 2(30,0)
  body extent -34,-19 34,19, height 39
0805_HV1 [mm] "Custom footprint based on analyzing multiple manufacturer recommendations"
  rrect10% 1x1.25 smd: 1(-1,0) 2(1,0)
  silkscreen extent -0.2,-0.75 0.2,0.75, body extent -1.1,-0.72 1.1,0.73, height 1.45
0805L [mm] "0805 from SM-752 data"
  rect 1.1x1.4 smd: 1(-0.75,0) 2(0.75,0)
  body extent -1.1,-0.72 1.1,0.72, height 1.45
1206 [mm] "1206 from SM-752 data"
  rect 1.3x1.85 smd: 1(-1.45,0) 2(1.45,0)
  silkscreen extent -2.4,-1.21 2.4,1.21, body extent -1.7,-0.9 1.7,0.9, height 1.35
1206_180L [mm] "1206_180"
  rect 1.1x1.75 smd: 1(-1.35,0) 2(1.35,0)
  silkscreen extent -0.4,-0.77 0.4,0.77, body extent -1.75,-0.95 1.75,0.95, height 1.8
1206L [mm] "1206 from SM-752 data"
  rect 1.1x1.75 smd: 1(-1.35,0) 2(1.35,0)
  silkscreen extent -0.4,-0.77 0.4,0.77, body extent -1.7,-0.9 1.7,0.9, height 1.35
1210_270L [mm] "1210"
  rect 1.1x2.6 smd: 1(-1.35,0) 2(1.35,0)
  silkscreen extent -0.4,-1.2 0.4,1.2, body extent -1.7,-1.35 1.7,1.35, height 2.7
1210_280 [mm] "SMD, 2-Leads, Body 3.6x2.8mm, Height 2.8mm"
  rect 1.1x2.2 smd: 1(-1.65,0) 2(1.65,0)
  silkscreen extent -0.84,-1.4 0.84,1.4, body extent -1.8,-1.4 1.8,1.4, height 2.8
1210L [mm] "1210 from SM-752 data"
  rect 1.1x2.6 smd: 1(-1.35,0) 2(1.35,0)
  silkscreen extent -0.4,-1.2 0.4,1.2, body extent -1.7,-1.35 1.7,1.35, height 1.35
AssemblyNote [mil] "Assembly Note"
C900_9x13 [mm] "Kemet"
  round 1.45 hole 0.85: 1(-5,0) 2(5,0)
  silkscreen extent -4.5,-2.75 4.5,2.76, body extent -4.49,-2.75 4.49,2.75, height 12.96
CE_Mark_5mm [mil] "Minimum text height for CE Mark"
  silkscreen extent -138,-98 138,98
DBZ0003A_L [mm] "SOT23, 3-Leads, Body 2.9x1.3mm, Pitch 0.95mm, Lead Span 2.4mm, IPC High Density"
  rrect18% 0.8x0.55 smd: 1(-1.1,0.95) 2(-1.1,-0.95) 3(1.1,0)
  silkscreen extent 0.2,-1.5 0.7,1.5, body extent -1.26,-1.46 1.26,1.46, height 0.98
DPAK [mm] "D-PAK, 3-Pads, Body 6.22x6.73mm (max), TO-252AA using nominal STEP model"
  rrect6% 2.6x1.6 smd: 1(-3.4,2.28) 3(-3.4,-2.28)
  rrect2% 6.2x5.8 smd paste-3: 2(3.4,0)
  body extent -3.86,-3.29 5.84,3.29, height 2.48
DWV0008A [mm] "SOIC, 8-Leads, Body 5.95x7.6mm (max), Pitch 1.27mm"
  rrect17% 1.8x0.6 smd: 1(-5.45,1.905) 2(-5.45,0.635) 3(-5.45,-0.635) 4(-5.45,-1.905) 5(5.45,-1.905) 6(5.45,-0.635) 7(5.45,0.635) 8(5.45,1.905)
  silkscreen extent -6.25,-2.95 2.98,2.95, body extent -5.77,-2.92 5.77,2.93, height 2.67
FCC_disclaimer [mil]
Fiducial6.4-20 [mil]
  round 25 smd mask+26.87: 1(0,0)
  Top Layer keep-out circle w46.37: c0,0 r19.68
FP-7447052_PTH_D10MM0-MFG [mm]
  rrect9% 1.15x1.15 hole 0.65 paste-1000: 1(0,2)
  round 1.15 hole 0.65 paste-1000: 2(0,-2)
  silkscreen extent -5,-2.75 5,2.75, body extent -5.1,-2.85 5.1,2.85, height 0.25
FP-CDSOD323-T18C_SOD323-MFG [mm]
  rrect20% 0.8x0.5 smd paste+0 mask+0: 1(-1.1,0) 2(1.1,0)
  silkscreen extent -0.95,-0.72 0.95,0.72, body extent -1.27,-0.65 1.27,0.65, height 1.14
FP-RLTI-1387_PTH_CMC_0IN38_0IN60-MFG [mm]
  rrect5% 2.05x2.05 hole 1.35 paste-1000: 1(-5.08,-3.175)
  round 2.05 hole 1.35 paste-1000: 2(-5.08,3.175) 3(5.08,3.175) 4(5.08,-3.175)
  silkscreen extent -7.62,-5.55 7.62,4.83, body extent -7.72,-4.93 7.72,4.93, height 0.25
FP-RLTI-1431_PTH8_1IN0_0IN91-MFG [mm]
  rrect7% 1.4x1.4 hole 0.9 paste-1000: 1(-1.803,9.957)
  round 1.4 hole 0.9 paste-1000: 2(-3.594,8.153) 3(-1.803,6.35) 5(1.803,9.957) 6(3.594,8.153) 7(1.803,6.35)
  rrect25% 1.27x1.651 hole 1 paste-1000 mask+0.05: 8(12.065,-0.813)
  rrect25% 4.572x3.048 hole 2.54 paste-1000: A(-7.747,-13.97) B(-1.905,-13.97)
  silkscreen extent -12.7,-11.56 12.7,12.09, body extent -12.8,-38.45 13.07,11.66, height 0.25
FP-TLP383(GR-TPL,E_SO6-4-MFG [mm]
  rrect13% 1.3x0.8 smd paste+0 mask+0: 1(-4.75,1.27) 3(-4.75,-1.27) 4(4.75,-1.27) 6(4.75,1.27)
  silkscreen extent -3.7,-2.02 3.7,2.02, body extent -5.01,-1.92 5.01,1.92, height 2.3
FUSE_392 [mm] "LITTELFUSE"
  round 1.7 hole 1.05: 1(-2.54,0) 2(2.54,0)
  silkscreen extent -4.32,-2.03 4.32,2.03, body extent -4.25,-2 4.25,2, height 8
IEC_Caution_Small [mil]
  silkscreen extent -107,-93 107,92
IEC_HighVoltage_Small [mil]
  silkscreen extent -107,-88 107,97
IEC_HotSurface_Small [mil]
  silkscreen extent -107,-93 107,92
Keystone5011 [mil] "Keystone Multipurpose loops"
  round 87 hole 63: 1(0,0)
  silkscreen extent -70,-70 70,70, body extent -63,-63 63,62, height 319
Keystone5012 [mil] "Keystone Multipurpose loops"
  round 87 hole 63: 1(0,0)
  silkscreen extent -70,-70 70,70, body extent -63,-63 63,62, height 319
Keystone_1902C [mil] "Hex Standoff, 4-40 threaded, nylon"
  round 1 on Mech4: 0(0,0)
  body extent -145,-126 146,126, height 501
Label_650x200 [mil] "Thermal Transfer Label"
  round 1 on Mech14: 0(0,0)
  silkscreen extent -325,-100 325,100, body extent -325,-100 325,100, height 1
"NY PMS 440 0025 PH" [mil] "4-40 nylon screw and mounting hole"
  round 175 hole 125: 1(0,0)
  body extent -130,-130 130,130, height 106
On-Shore_ED120_2DS [mm] "ONSHORE"
  rrect5% 2x2 hole 1.25: 1(-2.54,0)
  round 2 hole 1.25: 2(2.54,0)
  silkscreen extent -5.6,-4 5.12,5, body extent -5.78,-4 5.08,5, height 13
PG-TDSON-8 [mm] "Infineon recommended land pattern"
  rect 1.2x0.65 smd: 1(-2.825,1.905) 2(-2.825,0.635) 3(-2.825,-0.635) 4(-2.825,-1.905)
  rect 0.5x0.7 smd: 5(3.175,-2) 6(3.175,-0.675) 7(3.175,0.675) 8(3.175,2)
  rect 4.5x4.7 smd paste-2.25: 9(0.675,0)
  silkscreen extent -3.74,-3 3.74,3, body extent -3.18,-2.89 3.18,2.9, height 1.1
PSG_1000x1150 [mm] "United Chemi-Con"
  rrect7% 1.5x1.5 hole 0.85: 1(-2.5,0)
  round 1.5 hole 0.85: 2(2.5,0)
  silkscreen extent -5.3,-5.3 5.3,5.3, body extent -5.25,-5.25 5.25,5.25, height 13.01
RTW0024B-MFG [mm]
  rrect42% 0.6x0.24 smd paste+0 mask+0: 1(-1.9,1.25) 2(-1.9,0.75) 3(-1.9,0.25) 4(-1.9,-0.25) 5(-1.9,-0.75) 6(-1.9,-1.25) 13(1.9,-1.25) 14(1.9,-0.75) 15(1.9,-0.25) 16(1.9,0.25) 17(1.9,0.75) 18(1.9,1.25)
  rrect42% 0.24x0.6 smd paste+0 mask+0: 7(-1.25,-1.9) 8(-0.75,-1.9) 9(-0.25,-1.9) 10(0.25,-1.9) 11(0.75,-1.9) 12(1.25,-1.9) 19(1.25,1.9) 20(0.75,1.9) 21(0.25,1.9) 22(-0.25,1.9) 23(-0.75,1.9) 24(-1.25,1.9)
  rrect4% 2.45x2.45 smd paste-1000 mask+0: 25(0,0)
  silkscreen extent -2.62,-2.05 2.05,2.05, body extent -2,-2 2,2, height 0.8
Rubycon_1800x2500_HD [mm] "TH, 2-Leads, Dia 18mm, Pin Spacing 7.5mm"
  rrect50% 1.575x1.575 hole 1.05: 1(-3.75,0)
  round 1.575 hole 1.05: 2(3.75,0)
  body extent -9.25,-29.15 9.26,0.4, height 18.5
SMA [mm] "Molded Diode, 2-Leads, Body 4.3x2.6mm, IPC Medium Density, based on OnSemi component dimensions and land pattern"
  rect 2x2 smd: 1(-2,0) 2(2,0)
  silkscreen extent -3.66,-1.57 2.79,1.57, body extent -2.6,-1.3 2.6,1.3, height 2.42
SNT-100-BK-x-H [mil] "Shunt Connector, 2x1"
  round 1 on Mech3: 0(0,0)
  body extent -100,-50 100,50, height 650
SOD-123H [mm] "SMT, 2-Leads, Body 3.5x1.6mm"
  rect 1.3x1.8 smd: 1(-1.5,0) 2(1.5,0)
  silkscreen extent -2.9,-1.3 2.3,1.3, body extent -1.9,-0.9 1.9,0.9, height 1
SOD-323 [mm] "NXP recommended land pattern"
  rect 0.6x0.6 smd paste-0.05: 1(-1.1,0) 2(1.1,0)
  silkscreen extent -2.06,-0.86 1.53,0.86, body extent -1.3,-0.67 1.3,0.68, height 1.1
SOD-523 [mm] "NXP Semiconductor recommended land pattern, nominal STEP model"
  rect 0.8x0.6 smd paste-0.05: 1(-0.55,0) 2(0.55,0)
  silkscreen extent -1.65,-0.66 1.2,0.66, body extent -0.8,-0.4 0.8,0.4, height 0.72
SOT-23L [mm] "SOT23, 3-Leads, Body 2.9x1.3mm, Pitch 0.95mm, Lead Span 2.5mm, IPC High Density"
  rrect50% 0.8x0.6 smd: 1(-1.1,0.95) 2(-1.1,-0.95) 3(1.1,0)
  silkscreen extent -1.5,-1.5 0.7,1.5, body extent -1.16,-1.45 1.21,1.45, height 1
SOT-323 [mm] "Diodes Inc recommended land pattern.  2016-02-24"
  rrect21% 0.6x0.47 smd: 1(-0.95,0.65) 2(-0.95,-0.65) 3(0.95,0)
  silkscreen extent -1.14,-1.22 0.77,1.22, body extent -1.13,-1.13 1.12,1.12, height 1.13
TI_Stacked_Overlay_Small [mil]
  silkscreen extent -418,-98 418,98
TSW-103-07-G-S [mm] "Samtec 100mil, 1x3, 230 mil above insulator"
  rrect50% 1.65x1.65 hole 1.016: 1(-2.54,0)
  round 1.65 hole 1.016: 2(0,0) 3(2.54,0)
  body extent -3.81,-1.27 3.81,1.27, height 8.38
TUMD2SM [mm] "SMD, 2-Leads, Body 2x1.4mm"
  rrect12% 0.8x1.1 smd: 1(-1.15,0) 2(1.15,0)
  silkscreen extent -2.2,-0.95 1.55,0.95, body extent -1.35,-0.75 1.35,0.75, height 0.8
UVC_1000x1600 [mm] "TH, 2-Leads, Dia 10mm, Lead Spacing 5mm"
  rrect50% 1.275x1.275 hole 0.85: 1(-2.5,0)
  round 1.275 hole 0.85: 2(2.5,0)
  silkscreen extent -5.25,-5.25 5.25,5.25, body extent -5.25,-5.25 5.26,5.25, height 18.01
WCAP-FTX2_1500x850 [mm] "TH, 2-Leads, Body 15x8.5mm"
  rrect50% 1.35x1.35 hole 0.9: 1(-6.25,0)
  round 1.35 hole 0.9: 2(6.25,0)
  body extent -7.5,-4.25 7.5,4.25, height 14
WEEE_Minimum [mil] "WEEElie bin"
  silkscreen extent -95,-172 99,104
Z4-D [mm] "SMD, 4-Leads, Body 8.1x10.5mm"
  rect 4.7x2.4 smd: 1(-3.7,2.55) 2(3.7,2.55) 3(3.7,-2.55) 4(-3.7,-2.55)
  silkscreen extent -5.3,-4.07 5.3,4.1, body extent -5.3,-4.1 5.3,4.1, height 1.56

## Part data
C1: library part CMP-0860955-2, "CAP, AL, 15 µF, 400 V, +/- 20%, AEC-Q200 Grade 2, TH", Cap_Case=10x16, Manufacturer=Nichicon, Tolerance_%=20%, Value2=400V, ValueDisplayed=15µF
C2: library part CMP-0084285-1, "CAP, AL, 82 µF, 400 V, +/- 20%, TH", Cap_Case=18x25mm, Manufacturer=Rubycon, Tolerance_%=20%, Value2=400V, ValueDisplayed=82µF
C3: library part CMP-0084596-1, "CAP, Film, 0.33 µF, X2 275 VAC, +/- 10%, TH", Cap_Case=15x8.5mm, Manufacturer="Wurth Elektronik", Tolerance_%=10%, ValueDisplayed=0.33µF
C4 C5: library part CMP-0009076-1, "CAP, CERM, 0.1 uF, 630 V, +/- 10%, X7R, 1210", Cap_Case=1210, Manufacturer=Kemet, Supplier Part Number 1=399-13490-1-ND, TempCo=X7R, Tolerance_%=10%, Value1=Unknown, Value2=630V, ValueDisplayed=0.1uF
C6: library part CMP-0008909-2, "CAP, CERM, 1000 pF, 630 V, +/- 10%, X7R, 1206", Cap_Case=1206, Manufacturer=MuRata, Supplier Part Number 1=490-3506-1-ND, TempCo=X7R, Tolerance_%=10%, Value1=Unknown, Value2=630V, ValueDisplayed=1000pF
C7: library part CMP-0012176-3, "CAP, Aluminum Polymer, 680 uF, 20 V, +/- 20%, 0.012 ohm, TH", Cap_Case=10x11.5, Manufacturer=Chemi-Con, Supplier Part Number 1=565-3623-ND, Tolerance_%=20%, Value1="0.012 ohm", Value2=20V, ValueDisplayed=680uF
C8: library part CMP-0081062-1, "CAP, CERM, 10 µF, 25 V,+/- 5%, X7R, AEC-Q200 Grade 1, 1206", Cap_Case=1206_180, Manufacturer=Kemet, Supplier Part Number 1=399-15734-1-ND, TempCo=X7R, Tolerance_%=5%, Value2=25V, ValueDisplayed=10µF
C9 C26: library part CMP-0009224-2, "CAP, CERM, 22 uF, 25 V, +/- 10%, X7R, 1210", Cap_Case=1210, Manufacturer=MuRata, Supplier Part Number 1=490-5313-1-ND, TempCo=X7R, Tolerance_%=10%, Value1=Unknown, Value2=25V, ValueDisplayed=22uF
C10: library part CMP-0008658-2, "CAP, CERM, 10 uF, 50 V, +/- 10%, X5R, 1206", Cap_Case=1206_180, Manufacturer=TDK, Supplier Part Number 1=445-5998-1-ND, TempCo=X5R, Tolerance_%=10%, Value1="0.002229 ohm", Value2=50V, ValueDisplayed=10uF
C11 C17: library part CMP-0006675-2, "CAP, CERM, 0.1 uF, 50 V, +/- 20%, X7R, 0402", Cap_Case=0402, Manufacturer=MuRata, Supplier Part Number 1=490-10701-1-ND, TempCo=X7R, Tolerance_%=20%, Value1=Unknown, Value2=50V, ValueDisplayed=0.1uF
C12: library part CMP-0006648-2, "CAP, CERM, 0.22 uF, 16 V, +/- 10%, X7R, 0402", Cap_Case=0402, Manufacturer=MuRata, Supplier Part Number 1=490-5418-1-ND, TempCo=X7R, Tolerance_%=10%, Value1=Unknown, Value2=16V, ValueDisplayed=0.22uF
C13 C14: library part CMP-0006687-2, "CAP, CERM, 330 pF, 50 V, +/- 10%, X7R, 0402", Cap_Case=0402, Manufacturer=MuRata, Supplier Part Number 1=490-3247-1-ND, TempCo=X7R, Tolerance_%=10%, Value1=Unknown, Value2=50V, ValueDisplayed=330pF
C15: library part CMP-0008251-2, "CAP, CERM, 1000 pF, 250 V, +/- 10%, X7R, 0805", Cap_Case=0805, Manufacturer=MuRata, Supplier Part Number 1=490-3525-1-ND, TempCo=X7R, Tolerance_%=10%, Value1=Unknown, Value2=250V, ValueDisplayed=1000pF
C16: library part CMP-0008252-2, "CAP, CERM, 1500 pF, 250 V, +/- 10%, X7R, 0805", Cap_Case=0805, Manufacturer=MuRata, Supplier Part Number 1=490-3527-1-ND, TempCo=X7R, Tolerance_%=10%, Value1=Unknown, Value2=250V, ValueDisplayed=1500pF
C18 C22: library part CMP-0085817-1, "CAP, CERM, 22 µF, 35 V,+/- 20%, X5R, 1210", Cap_Case=1210, Manufacturer="Taiyo Yuden", TempCo=X5R, Tolerance_%=20%, Value2=35V, ValueDisplayed=22µF
C19 C21: library part CMP-0006410-2, "CAP, CERM, 100 pF, 50 V, +/- 5%, C0G/NP0, 0402", Cap_Case=0402, Manufacturer=MuRata, Supplier Part Number 1=81-GRM1555C1H101JA1D, TempCo=C0G/NP0, Tolerance_%=5%, Value1=Unknown, Value2=50V, ValueDisplayed=100pF
C20: library part CMP-0078358-1, "CAP, CERM, 2200 pF, X1 400 VAC/Y1 400 VAC, +/- 20%, Y5V, D9xL13mm", Cap_Case=9x13mm, Manufacturer=Kemet, Supplier Part Number 1=399-9487-1-ND, TempCo=Y5V, Tolerance_%=20%, ValueDisplayed=2200pF
C23: library part CMP-0007067-4, "CAP, CERM, 1 uF, 35 V, +/- 10%, X7R, AEC-Q200 Grade 1, 0603", Cap_Case=0603, Manufacturer=TDK, Supplier Part Number 1=445-174215-1-ND, TempCo=X7R, Tolerance_%=10%, Value1="0.005522 ohm", Value2=35V, ValueDisplayed=1uF
C24 C28: library part CMP-0006348-2, "CAP, CERM, 22 pF, 50 V, +/- 5%, C0G/NP0, AEC-Q200 Grade 1, 0402", Cap_Case=0402, Manufacturer=MuRata, Supplier Part Number 1=490-9648-1-ND, TempCo=C0G/NP0, Tolerance_%=5%, Value1=Unknown, Value2=50V, ValueDisplayed=22pF
C25: library part CMP-0006679-2, "CAP, CERM, 0.015 uF, 50 V, +/- 10%, X7R, 0402", Cap_Case=0402, Manufacturer=MuRata, Supplier Part Number 1=490-4517-1-ND, TempCo=X7R, Tolerance_%=10%, Value1=Unknown, Value2=50V, ValueDisplayed=0.015uF
C27: library part CMP-0006674-2, "CAP, CERM, 0.01 uF, 50 V, +/- 10%, X7R, 0402", Cap_Case=0402, Manufacturer=MuRata, Supplier Part Number 1=490-4516-1-ND, TempCo=X7R, Tolerance_%=10%, Value1=Unknown, Value2=50V, ValueDisplayed=0.01uF
D1 D2: library part CMP-0080762-2, "Diode, Standard Recovery Rectifier, 600 V, 0.2 A, 2x1.4mm", Manufacturer=Rohm, Value1=0.2A, Value2=2.2V
D3: library part CMP-0029199-2, "Diode, Superfast Rectifier, 200 V, 1 A, 3.5x1.6mm", Manufacturer="Comchip Technology", Value1=1A, Value2=0.95V
D5: library part CMP-0029006-2, "Diode, Ultrafast, 100 V, 0.25 A, SOD-323", Manufacturer=Nexperia, Value1=0.25A, Value2=1.4V
D6: library part CMP-0087587-1, "Diode, TVS, Bi, 18 V, SOD-323", Manufacturer="Bourns Inc."
D7: library part CMP-0028437-2, "Diode, Schottky, 40 V, 0.2 A, SOT-323", Manufacturer="Diodes Inc.", Value1=0.2A, Value2=0.8V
